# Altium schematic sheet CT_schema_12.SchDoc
size 281 x 153 mm
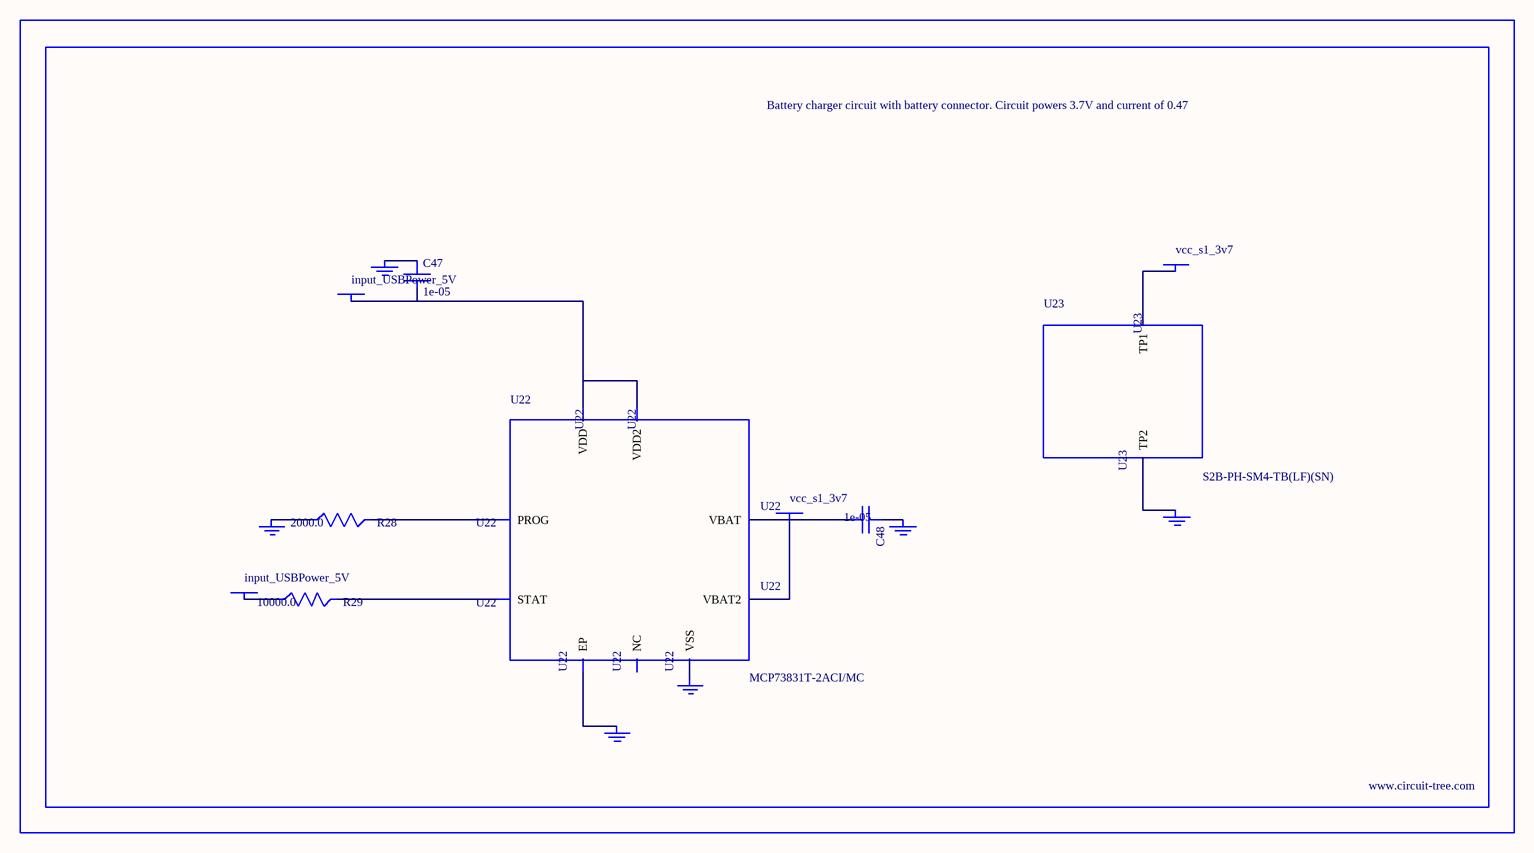
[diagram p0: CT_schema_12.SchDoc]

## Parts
BORDER11  (no value)
C47  1e-05  [C1206]
C48  1e-05  [C1206]
GND_INSTANCE_11_0  (no value)
GND_INSTANCE_11_1  (no value)
GND_INSTANCE_11_2  (no value)
GND_INSTANCE_11_3  (no value)
GND_INSTANCE_11_4  (no value)
GND_INSTANCE_11_5  (no value)
POWER_INSTANCE_11_0  input_USBPower_5V
POWER_INSTANCE_11_1  input_USBPower_5V
POWER_INSTANCE_11_2  vcc_s1_3v7
POWER_INSTANCE_11_3  vcc_s1_3v7
R28  2000.0  [R0603]
R29  10000.0  [R0603]
U22  MCP73831T-2ACI/MC  [DFN8_2X3MC]
U23  S2B-PH-SM4-TB(LF)(SN)  [JST-2-SMD]

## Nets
NetC47_1: C47.1 GND_INSTANCE_11_0.0(GND)
NetC47_2: C47.2 POWER_INSTANCE_11_0.0(PWR) U22.1(VDD) U22.2(VDD2)
NetC48_1: C48.1 GND_INSTANCE_11_1.0(GND)
NetC48_2: C48.2 POWER_INSTANCE_11_2.0(PWR) U22.3(VBAT) U22.4(VBAT2)
NetGND_INSTANCE_11_2_0: GND_INSTANCE_11_2.0(GND) R28.1
NetGND_INSTANCE_11_3_0: GND_INSTANCE_11_3.0(GND) U22.9(EP)
NetGND_INSTANCE_11_4_0: GND_INSTANCE_11_4.0(GND) U22.6(VSS)
NetGND_INSTANCE_11_5_0: GND_INSTANCE_11_5.0(GND) U23.2(TP2)
NetPOWER_INSTANCE_11_1_0: POWER_INSTANCE_11_1.0(PWR) R29.1
NetPOWER_INSTANCE_11_3_0: POWER_INSTANCE_11_3.0(PWR) U23.1(TP1)
NetR28_2: R28.2 U22.8(PROG)
NetR29_2: R29.2 U22.5(STAT)

Not connected (* = marked no-connect by the designer): U22 7(NC)

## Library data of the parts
BORDER11 = BORDER_PAGE11
C47 C48 = C1206C106K3RACTU
GND_INSTANCE_11_0-GND_INSTANCE_11_5 = GND
POWER_INSTANCE_11_0-POWER_INSTANCE_11_3 = PWR
R28 = RC0603JR-072KL
R29 = RC0603JR-0710KL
